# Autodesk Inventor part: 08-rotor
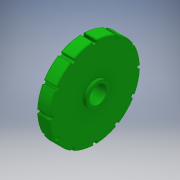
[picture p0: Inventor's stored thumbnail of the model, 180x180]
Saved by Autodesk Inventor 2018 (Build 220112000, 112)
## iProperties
Created: 2017-01
Part Number: 08-rotor
Material: Generic
Document SubType Name: Modeling
Designer: nicolas.scheffelmeie
Density: 1 g/cm^3
Appearance: Vert foncé
Author: nicolas.scheffelmeie
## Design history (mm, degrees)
sketch "Sketch1"
  geometry: C1 r 44.75 at (0, 0); C2 r 11.75 at (0, 0); 1 further point
  constraints: 2 centre point, 2 coincident
  dimensions: "d0" = 89.5 diameter of C1; "d1" = 23.5 diameter of C2
extrude "Extrusion1" new body sketch "Sketch1" distance "d2" = 13; taper "d3" = 0 deg
sketch "Sketch2"
  geometry: C1 r 11.75 at (0, 0); C2 r 8.75 at (0, 0); 1 further point
  constraints: 2 centre point, 2 coincident
  dimensions: "d4" = 23.5 diameter of C1; "d5" = 17.5 diameter of C2
extrude "Extrusion2" join sketch "Sketch2" distance "d6" = 16; taper "d7" = 0 deg
fillet "Fillet1" dims "d8" = 0.7
sketch "Sketch3"
  geometry: L1 (-44.727, -1.435)-(-41.785, -1.435); L2 (41.785, -1.435)-(58.974, -1.435); L3 (-44.727, 1.435)-(-41.785, 1.435); L4 (41.785, 1.435)-(61.672, 1.435); A1 r 44.75 centre (0, 0) between (-44.727, 1.435) and (-44.727, -1.435); A2 r 44.75 centre (0, 0) between (44.727, -1.435) and (44.727, 1.435); A3 r 41.81 centre (0, 0) between (41.785, -1.435) and (41.785, 1.435); A4 r 41.81 centre (0, 0) between (-41.785, 1.435) and (-41.785, -1.435); 1 further point
  constraints: 8 end point, 8 point on circle, 4 centre point, 4 horizontal, 2 coincident, 2 point on line
extrude "Extrusion3" cut sketch "Sketch3" extent not by distance; stored distance "d13" = 10; taper "d14" = 0 deg
fillet "Fillet2" dims "d15" = 0.7
pattern_circular "Circular Pattern1" dims angle "d17" = 360 deg
body "Solid1"
other parameters: "d9" = 1.435, "d10" = 1.435, "d11" = 83.62, "d12" = 89.5
